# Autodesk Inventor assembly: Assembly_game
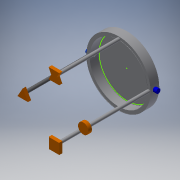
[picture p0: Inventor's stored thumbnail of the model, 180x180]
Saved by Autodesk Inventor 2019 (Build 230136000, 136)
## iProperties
Created: 2020-02
Part Number: Assembly_game
Document SubType Name: Assembly
Designer: Siddharth
Author: Siddharth
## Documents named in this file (10)
- D:\Assembly_game.iam
- D:\base_game.ipt
- D:\moving_plate_game.ipt
- D:\support_game.ipt
- D:\cross_pad.ipt
- D:\circlular_pad.iam
- D:\square_pad.ipt
- D:\trianglular_pad.ipt
- D:\GAME_MOTOR.ipt
- D:\GAME_BALLbearings.ipt
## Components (20 placed, 9 different names)
1. base_game:1
2. moving_plate_game:1
3. support_game:1
4. support_game:2
5. support_game:3
6. support_game:4
7. cross_pad:1
8. circlular_pad:1 [sub-assembly]
9. square_pad:1
10. trianglular_pad:1
11. GAME_MOTOR:1
12. GAME_MOTOR:5
13. GAME_BALLbearings:1
14. GAME_BALLbearings:2
15. GAME_BALLbearings:3
16. GAME_BALLbearings:4
17. GAME_BALLbearings:5
18. GAME_BALLbearings:6
19. GAME_BALLbearings:7
20. GAME_BALLbearings:8
